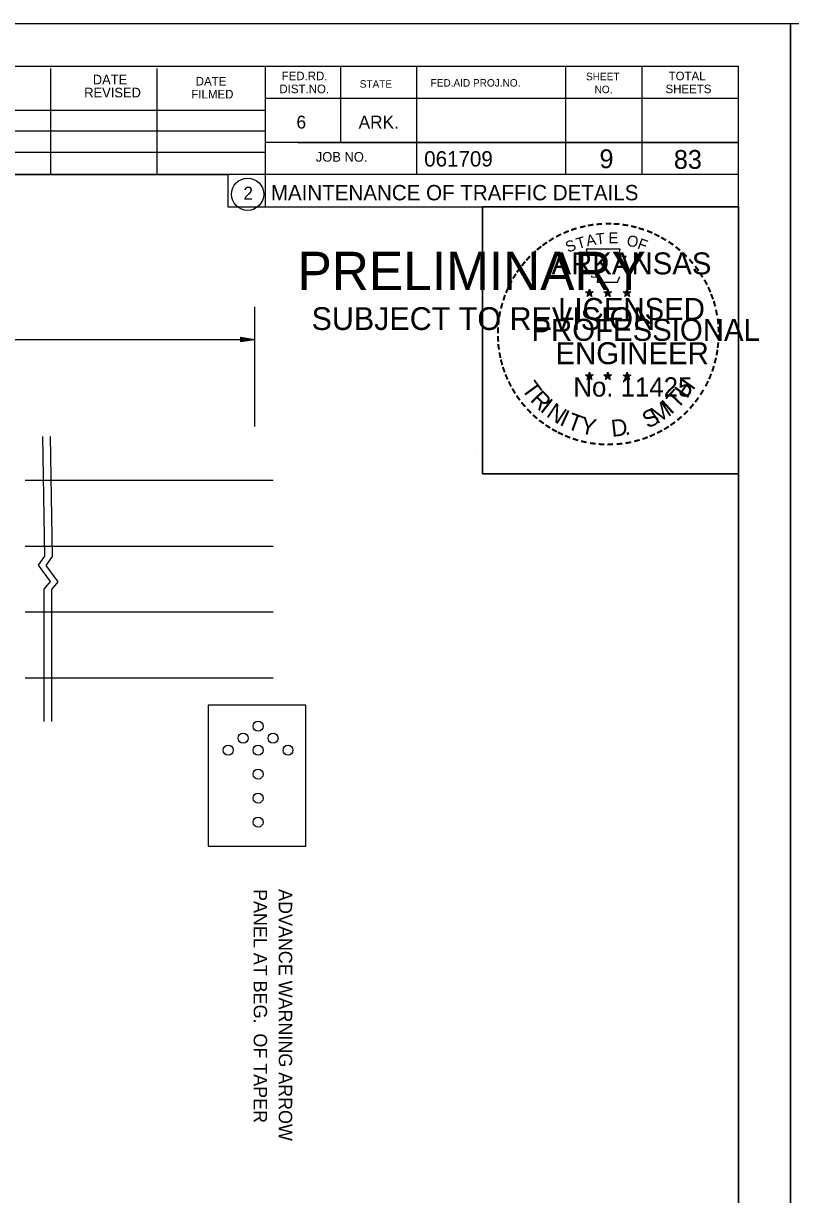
# Model space of a CAD drawing. Extents: x 1397271 to 1411271, y 376395 to 377888.
# Drawn here: x 1403782 to 1404271, y 377141 to 377888 of the extents above; entities that cross this region are included whole.
import ezdxf

# ---------------------------------------------------------------- set-up
doc = ezdxf.new("R2010")
doc.units = 0
for name, color, linetype in [('Default', 7, 'Continuous'), ('R_Border', 7, 'Continuous'), ('R_Border PE', 7, 'Continuous'), ('R_Border Prem', 7, 'Continuous'), ('R_Draft', 7, 'Continuous'), ('R_MOT', 7, 'Continuous'), ('R_No Plot', 7, 'Continuous')]:
    doc.layers.add(name, color=color, linetype=linetype)

msp = doc.modelspace()

# ---------------------------------------------------------------- linework, layer by layer
at = {"layer": 'Default'}
for p, q in [((1403929.34, 377707.31), (1403929.34, 377631.08)), ((1403728.23, 377686.54), (1403929.34, 377686.54)), ((1403920.27, 377687.9), (1403929.34, 377686.54)), ((1403920.27, 377687.9), (1403920.27, 377685.18)), ((1403920.27, 377687.67), (1403927.82, 377686.54)), ((1403920.27, 377687.44), (1403926.27, 377686.54)), ((1403920.27, 377687.22), (1403924.76, 377686.54)), ((1403920.27, 377686.98), (1403923.22, 377686.54)), ((1403920.27, 377686.75), (1403921.7, 377686.54)), ((1403920.27, 377685.18), (1403929.34, 377686.54)), ((1403920.27, 377686.1), (1403923.22, 377686.54)), ((1403920.27, 377685.64), (1403926.27, 377686.54)), ((1403920.27, 377685.41), (1403927.82, 377686.54)), ((1403920.27, 377685.86), (1403924.76, 377686.54)), ((1403920.27, 377686.33), (1403921.7, 377686.54)), ((1403782.89, 377596.8), (1403886.54, 377596.8)), ((1403886.54, 377596.8), (1403941.25, 377596.8)), ((1403782.89, 377554.76), (1403886.54, 377554.76)), ((1403886.54, 377554.76), (1403941.25, 377554.76)), ((1403782.89, 377512.73), (1403886.54, 377512.73)), ((1403886.54, 377512.73), (1403941.25, 377512.73)), ((1403782.89, 377470.69), (1403886.54, 377470.69)), ((1403886.54, 377470.69), (1403941.25, 377470.69))]:
    msp.add_line(p, q, dxfattribs=at)
at = {"layer": 'R_Border'}
for p, q in [((1402024.58, 377860.72), (1404237.88, 377860.72)), ((1403799.39, 377791.56), (1403799.39, 377859.32)), ((1403867.15, 377791.56), (1403867.15, 377859.32)), ((1403936.17, 377860.72), (1403936.17, 377771.12)), ((1403984.05, 377860.72), (1403984.05, 377812.14)), ((1404032.63, 377860.72), (1404032.63, 377791.56)), ((1404127.69, 377860.72), (1404127.69, 377791.56)), ((1404176.27, 377860.72), (1404176.27, 377791.56)), ((1404237.88, 376422.47), (1404237.88, 377860.72)), ((1404237.88, 377840.14), (1403936.17, 377840.14)), ((1404237.88, 377840.28), (1404237.88, 377840.28)), ((1403662.05, 377832.58), (1403936.17, 377832.58)), ((1403662.05, 377819.56), (1403936.17, 377819.56)), ((1403662.05, 377805.98), (1403936.17, 377805.98)), ((1404237.88, 377812.14), (1403936.17, 377812.14)), ((1403956.89, 377812.14), (1404237.88, 377812.14)), ((1404237.88, 377791.56), (1403662.05, 377791.56)), ((1403936.17, 377771.12), (1404237.88, 377771.12))]:
    msp.add_line(p, q, dxfattribs=at)
msp.add_circle((1403924.88, 377779.07), 10.27, dxfattribs=at)
at = {"layer": 'R_Border PE'}
for p, q in [((1404140.46, 377716.84), (1404142.9, 377716.06)), ((1404140.46, 377716.84), (1404142.23, 377716.53)), ((1404140.46, 377716.84), (1404142.11, 377715.99)), ((1404141.39, 377713.98), (1404142.9, 377716.06)), ((1404142.9, 377718.62), (1404142.61, 377716.85)), ((1404142.9, 377716.06), (1404142.9, 377718.62)), ((1404142.9, 377718.62), (1404143.24, 377716.87)), ((1404145.33, 377716.84), (1404142.9, 377716.06)), ((1404144.39, 377713.98), (1404142.9, 377716.06)), ((1404145.33, 377716.84), (1404143.33, 377716.5)), ((1404144.39, 377713.98), (1404143.43, 377716.02)), ((1404145.33, 377716.84), (1404143.9, 377716.13)), ((1404152.15, 377716.84), (1404154.59, 377716.06)), ((1404152.15, 377716.84), (1404153.92, 377716.53)), ((1404152.15, 377716.84), (1404153.8, 377715.99)), ((1404153.08, 377713.98), (1404154.59, 377716.06)), ((1404154.59, 377718.62), (1404154.3, 377716.85)), ((1404154.59, 377716.06), (1404154.59, 377718.62)), ((1404154.59, 377718.62), (1404154.93, 377716.87)), ((1404157.02, 377716.84), (1404154.59, 377716.06)), ((1404156.08, 377713.98), (1404154.59, 377716.06)), ((1404157.02, 377716.84), (1404155.02, 377716.5)), ((1404156.08, 377713.98), (1404155.12, 377716.02)), ((1404157.02, 377716.84), (1404155.59, 377716.13)), ((1404164.49, 377716.76), (1404166.94, 377715.98)), ((1404164.49, 377716.76), (1404166.27, 377716.44)), ((1404164.49, 377716.76), (1404166.15, 377715.9)), ((1404165.43, 377713.9), (1404166.94, 377715.98)), ((1404166.94, 377718.53), (1404166.65, 377716.77)), ((1404166.94, 377715.98), (1404166.94, 377718.53)), ((1404166.94, 377718.53), (1404167.28, 377716.78)), ((1404169.37, 377716.76), (1404166.94, 377715.98)), ((1404168.43, 377713.9), (1404166.94, 377715.98)), ((1404169.37, 377716.76), (1404167.36, 377716.41)), ((1404168.43, 377713.9), (1404167.47, 377715.94)), ((1404169.37, 377716.76), (1404167.94, 377716.04)), ((1404141.39, 377713.98), (1404142.27, 377715.69)), ((1404141.39, 377713.98), (1404142.88, 377715.5)), ((1404144.39, 377713.98), (1404142.88, 377715.48)), ((1404153.08, 377713.98), (1404153.96, 377715.69)), ((1404153.08, 377713.98), (1404154.57, 377715.5)), ((1404156.08, 377713.98), (1404154.57, 377715.48)), ((1404165.43, 377713.9), (1404166.31, 377715.61)), ((1404165.43, 377713.9), (1404166.92, 377715.42)), ((1404168.43, 377713.9), (1404166.92, 377715.4)), ((1404140.43, 377663.83), (1404142.87, 377663.05)), ((1404140.43, 377663.83), (1404142.2, 377663.51)), ((1404140.43, 377663.83), (1404142.09, 377662.97)), ((1404142.87, 377665.61), (1404142.58, 377663.84)), ((1404142.87, 377663.05), (1404142.87, 377665.61)), ((1404142.87, 377665.61), (1404143.21, 377663.86)), ((1404145.3, 377663.83), (1404142.87, 377663.05)), ((1404145.3, 377663.83), (1404143.3, 377663.49)), ((1404145.3, 377663.83), (1404143.87, 377663.11)), ((1404152.11, 377663.83), (1404154.55, 377663.05)), ((1404152.11, 377663.83), (1404153.88, 377663.51)), ((1404152.11, 377663.83), (1404153.77, 377662.97)), ((1404154.55, 377665.61), (1404154.27, 377663.84)), ((1404154.55, 377663.05), (1404154.55, 377665.61)), ((1404154.55, 377665.61), (1404154.9, 377663.86)), ((1404156.98, 377663.83), (1404154.55, 377663.05)), ((1404156.98, 377663.83), (1404154.98, 377663.49)), ((1404156.98, 377663.83), (1404155.55, 377663.11)), ((1404164.48, 377663.76), (1404166.92, 377662.98)), ((1404164.48, 377663.76), (1404166.25, 377663.44)), ((1404164.48, 377663.76), (1404166.14, 377662.9)), ((1404166.92, 377665.54), (1404166.64, 377663.77)), ((1404166.92, 377662.98), (1404166.92, 377665.54)), ((1404166.92, 377665.54), (1404167.27, 377663.79)), ((1404169.35, 377663.76), (1404166.92, 377662.98)), ((1404169.35, 377663.76), (1404167.35, 377663.42)), ((1404169.35, 377663.76), (1404167.92, 377663.04)), ((1404141.36, 377660.97), (1404142.87, 377663.05)), ((1404141.36, 377660.97), (1404142.24, 377662.68)), ((1404141.36, 377660.97), (1404142.86, 377662.49)), ((1404144.36, 377660.97), (1404142.86, 377662.47)), ((1404144.36, 377660.97), (1404142.87, 377663.05)), ((1404144.36, 377660.97), (1404143.4, 377663.01)), ((1404153.04, 377660.97), (1404154.55, 377663.05)), ((1404153.04, 377660.97), (1404153.92, 377662.68)), ((1404153.04, 377660.97), (1404154.54, 377662.49)), ((1404156.04, 377660.97), (1404154.54, 377662.47)), ((1404156.04, 377660.97), (1404154.55, 377663.05)), ((1404156.04, 377660.97), (1404155.09, 377663.01)), ((1404165.41, 377660.9), (1404166.92, 377662.98)), ((1404165.41, 377660.9), (1404166.29, 377662.61)), ((1404165.41, 377660.9), (1404166.91, 377662.42)), ((1404168.41, 377660.9), (1404166.91, 377662.4)), ((1404168.41, 377660.9), (1404166.92, 377662.98)), ((1404168.41, 377660.9), (1404167.46, 377662.94))]:
    msp.add_line(p, q, dxfattribs=at)
for points in [[(1404140.74, 377743.99), (1404142.63, 377738.2)], [(1404165.32, 377737.53), (1404166.31, 377739.52), (1404161.52, 377739.35), (1404162.56, 377743.99), (1404140.74, 377743.99)], [(1404144.19, 377727.03), (1404144.19, 377726.42), (1404148.13, 377726.28), (1404147.75, 377722.97), (1404160.84, 377722.97), (1404162.25, 377726.72)], [(1404142.9, 377718.62), (1404144.39, 377713.98), (1404140.46, 377716.84), (1404145.33, 377716.84), (1404141.39, 377713.98), (1404142.9, 377718.62)], [(1404154.59, 377718.62), (1404156.08, 377713.98), (1404152.15, 377716.84), (1404157.02, 377716.84), (1404153.08, 377713.98), (1404154.59, 377718.62)], [(1404166.94, 377718.53), (1404168.43, 377713.9), (1404164.49, 377716.76), (1404169.37, 377716.76), (1404165.43, 377713.9), (1404166.94, 377718.53)], [(1404142.87, 377665.61), (1404144.36, 377660.97), (1404140.43, 377663.83), (1404145.3, 377663.83), (1404141.36, 377660.97), (1404142.87, 377665.61)], [(1404154.55, 377665.61), (1404156.04, 377660.97), (1404152.11, 377663.83), (1404156.98, 377663.83), (1404153.04, 377660.97), (1404154.55, 377665.61)], [(1404166.92, 377665.54), (1404168.41, 377660.9), (1404164.48, 377663.76), (1404169.35, 377663.76), (1404165.41, 377660.9), (1404166.92, 377665.54)]]:
    msp.add_lwpolyline(points, dxfattribs=at)
for centre, radius in [((1404142.89, 377716.06), 1.21), ((1404142.89, 377716.06), 1.01), ((1404142.89, 377716.06), 0.81), ((1404142.89, 377716.06), 0.694), ((1404142.89, 377716.06), 0.523), ((1404142.89, 377716.06), 0.347), ((1404142.89, 377716.06), 0.208), ((1404154.58, 377716.06), 1.21), ((1404154.58, 377716.06), 1.01), ((1404154.58, 377716.06), 0.81), ((1404154.58, 377716.06), 0.694), ((1404154.58, 377716.06), 0.523), ((1404154.58, 377716.06), 0.347), ((1404154.58, 377716.06), 0.208), ((1404166.93, 377715.97), 1.21), ((1404166.93, 377715.97), 1.01), ((1404166.93, 377715.97), 0.81), ((1404166.93, 377715.97), 0.694), ((1404166.93, 377715.97), 0.523), ((1404166.93, 377715.97), 0.347), ((1404166.93, 377715.97), 0.208), ((1404142.86, 377663.05), 1.21), ((1404142.86, 377663.05), 1.01), ((1404142.86, 377663.05), 0.81), ((1404142.86, 377663.05), 0.694), ((1404154.55, 377663.05), 1.21), ((1404154.55, 377663.05), 1.01), ((1404154.55, 377663.05), 0.81), ((1404154.55, 377663.05), 0.694), ((1404166.92, 377662.98), 1.21), ((1404166.92, 377662.98), 1.01), ((1404166.92, 377662.98), 0.81), ((1404166.92, 377662.98), 0.694), ((1404142.86, 377663.05), 0.523), ((1404142.86, 377663.05), 0.347), ((1404142.86, 377663.05), 0.208), ((1404154.55, 377663.05), 0.523), ((1404154.55, 377663.05), 0.347), ((1404154.55, 377663.05), 0.208), ((1404166.92, 377662.98), 0.523), ((1404166.92, 377662.98), 0.347), ((1404166.92, 377662.98), 0.208)]:
    msp.add_circle(centre, radius, dxfattribs=at)
at = {"layer": 'R_MOT'}
for points in [[(1403794.14, 377624.62), (1403795.3, 377548.39), (1403791.38, 377542.55), (1403799.03, 377532.09), (1403795, 377527.25), (1403794.98, 377442.87)], [(1403798.97, 377624.62), (1403800.13, 377548.19), (1403796.21, 377542.35), (1403803.86, 377531.89), (1403799.83, 377527.05), (1403799.82, 377442.87)]]:
    msp.add_lwpolyline(points, dxfattribs=at)
msp.add_lwpolyline([(1403899.71, 377453.42), (1403899.71, 377363.39), (1403962, 377363.39), (1403962, 377453.42)], close=True, dxfattribs=at)
for centre in [(1403931.56, 377439.93), (1403922.02, 377432.29), (1403941.1, 377432.29), (1403912.48, 377424.64), (1403931.56, 377424.64), (1403950.64, 377424.64), (1403931.56, 377409.35), (1403931.56, 377394.06), (1403931.56, 377378.77)]:
    msp.add_circle(centre, 3.17, dxfattribs=at)
at = {"layer": 'R_No Plot'}
for p, q in [((1401937.77, 377887.98), (1404271.14, 377887.98)), ((1404070.1, 377613.86), (1404070.1, 377613.86))]:
    msp.add_line(p, q, dxfattribs=at)
for points in [[(1401937.72, 377887.98), (1404271.14, 377887.98), (1404271.14, 376394.59), (1401937.72, 376394.59)], [(1404271.14, 377887.98), (1406604.57, 377887.98), (1406604.57, 376394.59), (1404271.14, 376394.59)], [(1403662.05, 377860.72), (1403662.05, 377791.56), (1403912.17, 377791.56), (1403912.17, 377771.12), (1404074.57, 377771.12), (1404074.57, 377600.79), (1404237.88, 377600.79), (1404237.88, 376422.47), (1402024.58, 376422.47), (1402024.58, 377860.72)], [(1404074.57, 377771.34), (1404237.88, 377771.34), (1404237.88, 377600.79), (1404074.57, 377600.79)]]:
    msp.add_lwpolyline(points, close=True, dxfattribs=at)

# ---------------------------------------------------------------- texts
at = {"layer": 'R_Border'}
for s, height, p in [('DATE', 6.155, (1403826.13, 377849.1)), ('DATE', 5.474, (1403891.79, 377848.4)), ('FED.RD.', 5.474, (1403946.53, 377851.76)), ('STATE', 4.788, (1403996.37, 377847)), ('FED.AID PROJ.NO.', 4.7881, (1404041.59, 377847.7)), ('SHEET', 4.788, (1404140.71, 377851.76)), ('TOTAL', 5.474, (1404193.36, 377851.76)), ('REVISED', 6.155, (1403820.67, 377840.84)), ('FILMED', 5.474, (1403888.99, 377840.14)), ('DIST.NO.', 5.474, (1403945.13, 377843.5)), ('NO.', 4.788, (1404146.17, 377843.5)), ('SHEETS', 5.474, (1404191.4, 377843.5)), ('6', 8.21, (1403956.05, 377820.96)), ('ARK.', 8.206, (1403995.67, 377820.96)), ('JOB NO.', 6.155, (1403968.37, 377799.82)), ('061709', 9.8, (1404037.5, 377796.74)), ('2', 8.21, (1403922.2, 377775.66)), ('MAINTENANCE OF TRAFFIC DETAILS', 9.8002, (1403939.68, 377775.2))]:
    msp.add_text(s, height=height, rotation=360, dxfattribs=at).set_placement(p)
at = {"layer": 'R_Border PE'}
for s, height, rotation, p in [('-', 11.2, 5.89682, (1404147.08, 377755.47)), ('-', 11.2, 0.18623, (1404152.48, 377755.97)), ('-', 11.2, 357.74304, (1404157.54, 377755.88)), ('-', 11.2, 28.79182, (1404123.11, 377747.77)), ('-', 11.2, 24.30721, (1404127.54, 377749.99)), ('-', 11.2, 19.17608, (1404131.98, 377751.88)), ('-', 11.2, 13.63015, (1404137.23, 377753.56)), ('A', 7, 11.21318, (1404141.41, 377745.81)), ('-', 11.2, 10.21935, (1404141.97, 377754.7)), ('T', 7, 6.02276, (1404147.35, 377746.97)), ('E', 7, 0.83234, (1404155.08, 377747.74)), ('-', 11.2, 352.16172, (1404162.75, 377755.49)), ('-', 11.2, 347.20489, (1404167.78, 377754.69)), ('-', 11.2, 342.3362, (1404172.23, 377753.61)), ('-', 11.2, 337.85509, (1404177.37, 377752.04)), ('-', 11.2, 334.12109, (1404181.79, 377750.15)), ('-', 11.2, 38.95066, (1404111.55, 377739.77)), ('-', 11.2, 36.23174, (1404114.88, 377742.42)), ('-', 11.2, 34.06357, (1404118.93, 377745.18)), ('S', 7, 21.59401, (1404129.23, 377741.73)), ('T', 7, 16.4036, (1404135.62, 377744.05)), ('O', 7, 350.4515, (1404166.31, 377746.27)), ('F', 7, 340.07066, (1404172.99, 377744.67)), ('-', 11.2, 329.64089, (1404185.84, 377748.17)), ('-', 11.2, 325.86266, (1404190.34, 377745.64)), ('-', 11.2, 320.52971, (1404194.61, 377742.66)), ('-', 11.2, 48.42305, (1404105.38, 377733.51)), ('-', 11.2, 42.96224, (1404108.52, 377736.85)), ('ARKANSAS', 14, 360, (1404118.71, 377727.97)), ('-', 11.2, 315.57859, (1404198.81, 377739.24)), ('-', 11.2, 54.23247, (1404099.67, 377726.14)), ('-', 11.2, 50.61417, (1404102.56, 377730.11)), ('-', 11.2, 309.87973, (1404202.79, 377735.39)), ('-', 11.2, 306.65218, (1404206.47, 377731.18)), ('-', 11.2, 62.87135, (1404095.21, 377718.15)), ('-', 11.2, 58.07063, (1404097.4, 377722.45)), ('-', 9.8, 303.67529, (1404209.87, 377727.2)), ('-', 11.2, 299.66835, (1404212.1, 377722.95)), ('-', 11.2, 67.77427, (1404093.39, 377713.87)), ('DWB', 0.07, 360, (1404142.81, 377716.03)), ('DWB', 0.07, 360, (1404154.5, 377716.03)), ('DWB', 0.07, 360, (1404166.85, 377715.95)), ('-', 11.2, 294.66279, (1404214.37, 377718.67)), ('-', 11.2, 75.46096, (1404090.48, 377704.46)), ('-', 11.2, 72.39447, (1404091.86, 377709.46)), ('LICENSED', 14, 360, (1404122.9, 377698.93)), ('-', 11.2, 290.57283, (1404216.17, 377714.63)), ('-', 11.2, 285.12326, (1404217.81, 377710.57)), ('-', 11.2, 81.20126, (1404089.56, 377699.47)), ('-', 11.2, 280.54934, (1404219.21, 377705.37)), ('-', 11.2, 89.06224, (1404088.85, 377689.73)), ('-', 11.2, 85.18634, (1404089.02, 377694.64)), ('PROFESSIONAL', 14.0002, 360, (1404105.93, 377685.6)), ('-', 11.2, 276.59616, (1404220.34, 377700)), ('-', 11.2, 274.33011, (1404220.76, 377694.94)), ('-', 11.2, 94.19588, (1404089.09, 377684.65)), ('-', 11.2, 269.94067, (1404221, 377690.52)), ('-', 11.2, 98.94793, (1404089.6, 377679.99)), ('ENGINEER', 14, 360, (1404121.24, 377670.72)), ('-', 11.2, 260.99529, (1404220.37, 377681.28)), ('-', 11.2, 263.5172, (1404220.86, 377685.86)), ('-', 11.2, 101.71495, (1404090.54, 377674.85)), ('-', 11.2, 105.45785, (1404091.68, 377670.69)), ('-', 11.2, 255.7626, (1404219.6, 377676.53)), ('-', 11.2, 109.08742, (1404093.18, 377666.27)), ('-', 11.2, 114.06432, (1404094.96, 377662.1)), ('-', 11.2, 247.88866, (1404216.77, 377666.78)), ('-', 11.2, 252.86809, (1404218.33, 377671.49)), ('-', 11.2, 115.72885, (1404097.1, 377657.77)), ('T', 10.78, 306.04056, (1404099.19, 377654.92)), ('No. 11425', 12.299, 360, (1404132.63, 377650.07)), ('DWB', 0.07, 360, (1404142.78, 377663.02)), ('DWB', 0.07, 360, (1404154.46, 377663.02)), ('DWB', 0.07, 360, (1404166.83, 377662.95)), ('H', 10.78, 54.60883, (1404205.03, 377648.16)), ('-', 11.2, 244.61971, (1404214.94, 377662.38)), ('-', 11.2, 120.44712, (1404099.59, 377653.67)), ('-', 11.2, 125.89344, (1404102.42, 377649.74)), ('R', 10.78, 314.00497, (1404104.52, 377647.58)), ('I', 10.78, 321.96938, (1404110.83, 377641.06)), ('T', 10.78, 46.64442, (1404198.8, 377641.57)), ('-', 11.2, 233.84524, (1404209.36, 377652.54)), ('-', 11.2, 239.07125, (1404212.18, 377657.12)), ('-', 11.2, 130.71812, (1404105.65, 377645.88)), ('-', 11.2, 134.22381, (1404109.27, 377642.07)), ('N', 10.78, 326.50021, (1404114.8, 377637.76)), ('I', 10.78, 335.36034, (1404123.26, 377632.26)), ('S', 10.78, 26.9312, (1404180.01, 377629.45)), ('M', 10.78, 32.65632, (1404185.88, 377632.29)), ('I', 10.78, 42.11359, (1404194.87, 377638.22)), ('-', 11.2, 225.76533, (1404203, 377644.63)), ('-', 11.2, 231.25377, (1404206.35, 377648.58)), ('-', 11.2, 138.93382, (1404112.94, 377638.82)), ('-', 11.2, 144.64634, (1404116.84, 377635.98)), ('T', 10.78, 339.89117, (1404127.88, 377629.96)), ('Y', 10.78, 347.85558, (1404136.4, 377626.85)), ('D', 10.78, 6.39691, (1404157.3, 377624.34)), ('-', 11.2, 215.73633, (1404195.5, 377637.77)), ('-', 11.2, 221.08509, (1404199.35, 377641.07)), ('-', 11.2, 148.08978, (1404120.76, 377633.38)), ('-', 11.2, 151.57039, (1404124.82, 377631.1)), ('-', 11.2, 154.60019, (1404128.47, 377629.37)), ('.', 10.78, 13.76417, (1404165.64, 377625.23)), ('-', 11.2, 204.25161, (1404183.49, 377630.4)), ('-', 11.2, 207.35684, (1404187.86, 377632.64)), ('-', 11.2, 212.24909, (1404191.77, 377635.06)), ('-', 11.2, 158.56121, (1404132.84, 377627.6)), ('-', 11.2, 162.79826, (1404137.65, 377626.11)), ('-', 11.2, 167.55551, (1404142.65, 377624.96)), ('-', 11.2, 173.11546, (1404148.06, 377624.19)), ('-', 11.2, 176.51827, (1404153.29, 377623.82)), ('-', 11.2, 181.59176, (1404158.5, 377623.95)), ('-', 11.2, 185.81666, (1404164.16, 377624.48)), ('-', 11.2, 191.28576, (1404169.32, 377625.41)), ('-', 11.2, 195.47429, (1404174.42, 377626.8)), ('-', 11.2, 200.71842, (1404179.16, 377628.49))]:
    msp.add_text(s, height=height, rotation=rotation, dxfattribs=at).set_placement(p)
at = {"layer": 'R_Border Prem'}
for s, height, p in [('PRELIMINARY', 24.5005, (1403956.74, 377717.92)), ('DWB', 0.07, (1403958.23, 377730.85)), ('SUBJECT TO REVISION', 14.5261, (1403965.66, 377692.52))]:
    msp.add_text(s, height=height, rotation=360, dxfattribs=at).set_placement(p)
at = {"layer": 'R_Draft'}
for s, p in [('9', (1404149.29, 377795.68)), ('83', (1404196.74, 377795.27))]:
    msp.add_text(s, height=12, rotation=360, dxfattribs=at).set_placement(p)
at = {"layer": 'R_MOT'}
for s, p in [('PANEL AT BEG.  OF TAPER', (1403928.74, 377336.05)), ('ADVANCE WARNING ARROW', (1403944.75, 377336.05))]:
    msp.add_text(s, height=8.5402, rotation=270, dxfattribs=at).set_placement(p)

doc.saveas('drawing.dxf')
